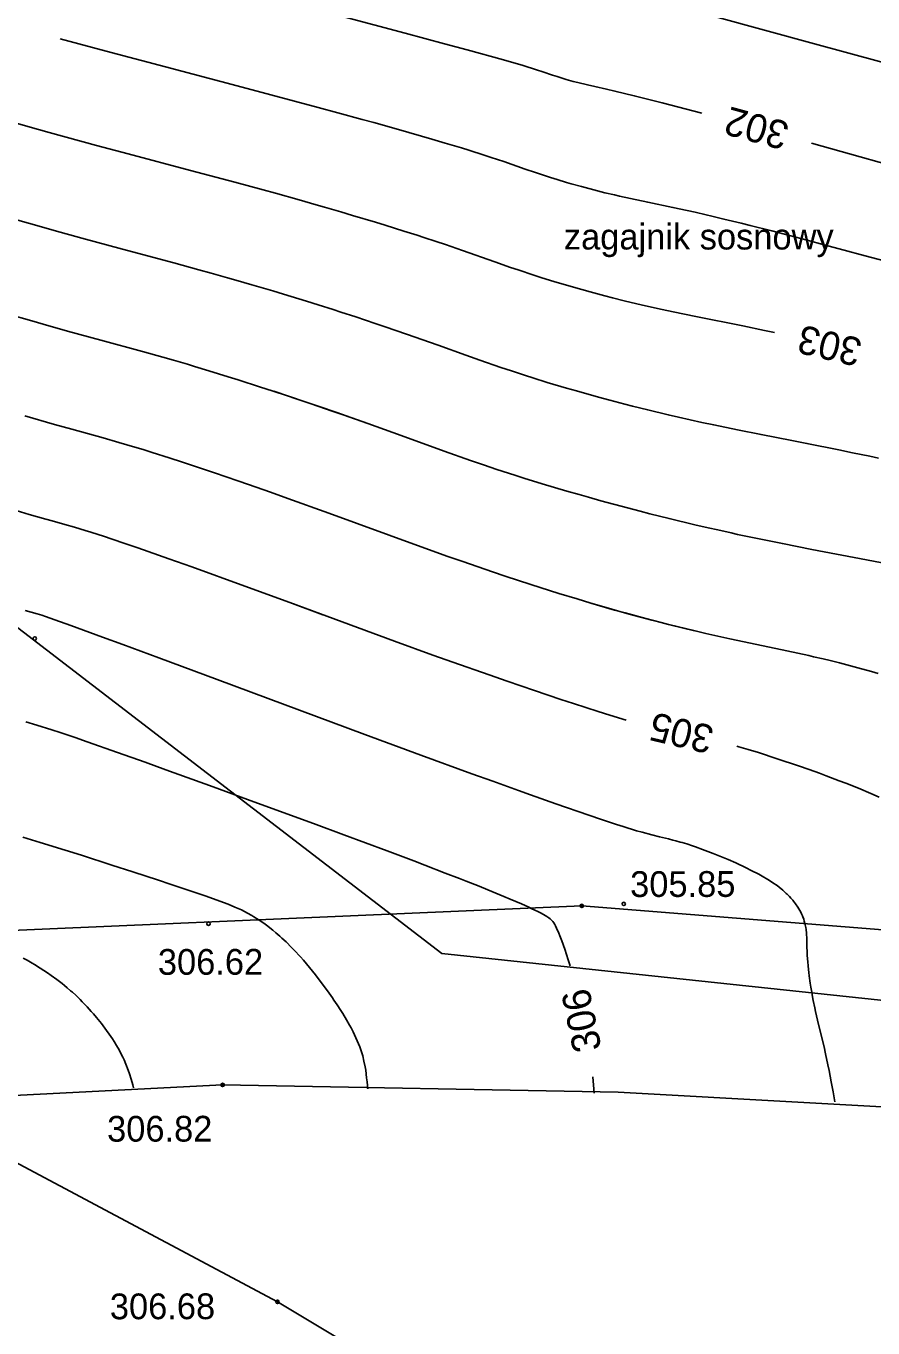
# Model space of a CAD drawing. Extents: x 7477803 to 7478145, y 5500698 to 5500984.
# Drawn here: x 7477935.87 to 7477958.24, y 5500809.46 to 5500843.86 of the extents above; entities that cross this region are included whole.
import ezdxf

# ---------------------------------------------------------------- set-up
doc = ezdxf.new("R2010")
doc.units = 0
for name, color, linetype in [('203-Punkt załamania granicy działki nie stabilizowany', 7, 'Continuous'), ('gr_dzialki', 7, 'Continuous'), ('gr_klasy', 7, 'Continuous'), ('jezdnia', 7, 'Continuous'), ('pkt_wys', 7, 'Continuous'), ('uwagi_projektanci', 7, 'Continuous'), ('warst_ciagla', 7, 'Continuous'), ('warst_opis', 7, 'Continuous'), ('warst_pogrub', 7, 'Continuous'), ('warst_przeryw', 7, 'Continuous')]:
    doc.layers.add(name, color=color, linetype=linetype)

# ---------------------------------------------------------------- blocks, each defined once
blk = doc.blocks.new('203')
blk.add_circle((0, 0), 0.045)
blk = doc.blocks.new('801_1')
at = {"layer": 'pkt_wys'}
blk.add_circle((0, 0), 0.045, dxfattribs=at)
blk.add_circle((0, 0), 0.045, dxfattribs=at)

msp = doc.modelspace()

# ---------------------------------------------------------------- linework, layer by layer
at = {"layer": 'gr_dzialki'}
for points in [[(7477950.55, 5500820.61), (7477930.18, 5500819.73)], [(7477982.46, 5500818.07), (7477950.55, 5500820.61)], [(7477942.51, 5500810.15), (7477926.59, 5500818.63)], [(7477942.51, 5500810.15), (7477965.87, 5500796.14)]]:
    msp.add_lwpolyline(points, dxfattribs=at)
at = {"layer": 'gr_klasy'}
for points in [[(7477930.18, 5500819.73), (7477950.55, 5500820.61)], [(7477950.55, 5500820.61), (7477982.46, 5500818.07)]]:
    msp.add_lwpolyline(points, dxfattribs=at)
at = {"layer": 'jezdnia'}
msp.add_lwpolyline([(7477875.926, 5500787.879), (7477876.814, 5500788.851), (7477888.353, 5500798.574), (7477893.52, 5500801.94), (7477899.965, 5500805.717), (7477906.333, 5500808.394), (7477918.837, 5500813.137), (7477925.266, 5500814.534), (7477933.655, 5500815.503), (7477941.064, 5500815.881), (7477951.515, 5500815.693), (7477966.065, 5500814.879), (7477981.427, 5500813.916), (7477996.758, 5500812.562), (7478008.149, 5500811.845)], dxfattribs=at)
at = {"layer": 'uwagi_projektanci'}
msp.add_lwpolyline([(7477973.16, 5500821.11), (7477976.42, 5500829.04), (7477976.7, 5500837.68), (7477975.34, 5500846.14), (7477969.75, 5500849.6), (7477966.4, 5500846.83), (7477944.18, 5500852.96), (7477931.39, 5500854.5), (7477929.49, 5500844.63), (7477930.21, 5500832.13), (7477946.85, 5500819.35), (7477963.16, 5500817.62)], close=True, dxfattribs=at)
at = {"layer": 'warst_ciagla'}
for points in [[(7477953.722, 5500841.553), (7477952.671, 5500841.827), (7477951.937, 5500842.014), (7477951.426, 5500842.139), (7477951.201, 5500842.191), (7477950.897, 5500842.256), (7477950.702, 5500842.3), (7477950.447, 5500842.363), (7477950.322, 5500842.396), (7477950.138, 5500842.449), (7477949.897, 5500842.523), (7477949.779, 5500842.562), (7477949.524, 5500842.649), (7477949.355, 5500842.704), (7477949.001, 5500842.813), (7477948.483, 5500842.963), (7477947.523, 5500843.229), (7477946.927, 5500843.391), (7477945.889, 5500843.669), (7477944.234, 5500844.107)], [(7477955.638, 5500835.757), (7477955.376, 5500835.814), (7477954.802, 5500835.934), (7477953.56, 5500836.185), (7477952.96, 5500836.309), (7477952.678, 5500836.369), (7477952.152, 5500836.486), (7477951.667, 5500836.601), (7477951.36, 5500836.677), (7477951.161, 5500836.729), (7477950.771, 5500836.833), (7477950.554, 5500836.893), (7477950.267, 5500836.975), (7477950.124, 5500837.016), (7477949.841, 5500837.101), (7477949.467, 5500837.217), (7477949.282, 5500837.276), (7477948.868, 5500837.413), (7477948.664, 5500837.482), (7477948.254, 5500837.626), (7477947.404, 5500837.926), (7477946.948, 5500838.083), (7477946.708, 5500838.164), (7477946.376, 5500838.274), (7477946.204, 5500838.329), (7477945.85, 5500838.442), (7477945.356, 5500838.596), (7477945.099, 5500838.675), (7477944.498, 5500838.855), (7477944.185, 5500838.948), (7477943.755, 5500839.072), (7477943.535, 5500839.136), (7477943.083, 5500839.264), (7477942.459, 5500839.438), (7477942.137, 5500839.527), (7477941.39, 5500839.731), (7477940.212, 5500840.045), (7477938.569, 5500840.481), (7477937.734, 5500840.705), (7477936.479, 5500841.049), (7477935.921, 5500841.204), (7477935.177, 5500841.414)], [(7477961.921, 5500839.278), (7477957.904, 5500840.402), (7477956.615, 5500840.759)], [(7477935.403, 5500836.246), (7477936.026, 5500836.065), (7477936.324, 5500835.979), (7477936.964, 5500835.799), (7477937.849, 5500835.556), (7477938.946, 5500835.258), (7477939.488, 5500835.107), (7477939.763, 5500835.028), (7477940.133, 5500834.92), (7477940.321, 5500834.864), (7477940.7, 5500834.75), (7477941.213, 5500834.592), (7477941.474, 5500834.51), (7477942.068, 5500834.32), (7477942.37, 5500834.222), (7477942.777, 5500834.087), (7477942.983, 5500834.018), (7477943.398, 5500833.877), (7477943.961, 5500833.684), (7477944.245, 5500833.584), (7477944.895, 5500833.354), (7477945.556, 5500833.115), (7477946.456, 5500832.79), (7477946.913, 5500832.626), (7477947.607, 5500832.383), (7477947.958, 5500832.263), (7477948.311, 5500832.145), (7477948.785, 5500831.991), (7477949.024, 5500831.915), (7477949.504, 5500831.766), (7477950.152, 5500831.572), (7477950.478, 5500831.477), (7477950.724, 5500831.407), (7477951.053, 5500831.315), (7477951.219, 5500831.27), (7477951.593, 5500831.169), (7477952.095, 5500831.037), (7477952.348, 5500830.972), (7477952.856, 5500830.845), (7477953.54, 5500830.682), (7477953.885, 5500830.602), (7477954.145, 5500830.543), (7477954.493, 5500830.466), (7477954.668, 5500830.428), (7477955.063, 5500830.344), (7477955.851, 5500830.182), (7477956.626, 5500830.029), (7477958.075, 5500829.751), (7477960.518, 5500829.287)], [(7477942.415, 5500834.207), (7477943.221, 5500833.938), (7477943.585, 5500833.813), (7477944.078, 5500833.643), (7477944.327, 5500833.555), (7477944.895, 5500833.354), (7477945.556, 5500833.115), (7477946.456, 5500832.79), (7477946.913, 5500832.626), (7477947.607, 5500832.383), (7477947.958, 5500832.263), (7477948.311, 5500832.145), (7477948.785, 5500831.991), (7477949.024, 5500831.915), (7477949.504, 5500831.766), (7477950.152, 5500831.572), (7477950.478, 5500831.477), (7477950.724, 5500831.407), (7477951.053, 5500831.315), (7477951.219, 5500831.27), (7477951.593, 5500831.169), (7477952.095, 5500831.037), (7477952.348, 5500830.972), (7477952.856, 5500830.845), (7477953.54, 5500830.682), (7477953.885, 5500830.602), (7477954.145, 5500830.543), (7477954.493, 5500830.466), (7477954.668, 5500830.428), (7477955.063, 5500830.344), (7477955.851, 5500830.182), (7477956.626, 5500830.029), (7477958.075, 5500829.751), (7477960.518, 5500829.287)], [(7477950.24, 5500819.03), (7477950.191, 5500819.188), (7477950.101, 5500819.465), (7477950.02, 5500819.692), (7477949.971, 5500819.819), (7477949.941, 5500819.893), (7477949.886, 5500820.019), (7477949.853, 5500820.088), (7477949.836, 5500820.118), (7477949.811, 5500820.16), (7477949.783, 5500820.198), (7477949.768, 5500820.217), (7477949.734, 5500820.251), (7477949.715, 5500820.268), (7477949.683, 5500820.294), (7477949.628, 5500820.332), (7477949.585, 5500820.359), (7477949.481, 5500820.417), (7477949.386, 5500820.465), (7477949.235, 5500820.538), (7477949.149, 5500820.578), (7477948.957, 5500820.664), (7477948.658, 5500820.793), (7477948.491, 5500820.863), (7477948.069, 5500821.036), (7477947.836, 5500821.13), (7477947.5, 5500821.263), (7477947.322, 5500821.333), (7477946.946, 5500821.479), (7477946.401, 5500821.688), (7477946.111, 5500821.799), (7477945.413, 5500822.062), (7477944.264, 5500822.49), (7477943.464, 5500822.785), (7477941.889, 5500823.362), (7477940.817, 5500823.753), (7477939.565, 5500824.207), (7477939.015, 5500824.405), (7477938.285, 5500824.665), (7477937.489, 5500824.946), (7477937.167, 5500825.057), (7477936.772, 5500825.19), (7477936.552, 5500825.262), (7477936.16, 5500825.386), (7477935.867, 5500825.475)], [(7477935.795, 5500819.231), (7477935.897, 5500819.175), (7477936.031, 5500819.098), (7477936.098, 5500819.059), (7477936.246, 5500818.967), (7477936.442, 5500818.839), (7477936.538, 5500818.773), (7477936.68, 5500818.67), (7477936.821, 5500818.562), (7477936.89, 5500818.506), (7477936.958, 5500818.449), (7477937.049, 5500818.371), (7477937.094, 5500818.332), (7477937.182, 5500818.25), (7477937.299, 5500818.138), (7477937.356, 5500818.081), (7477937.484, 5500817.948), (7477937.595, 5500817.825), (7477937.651, 5500817.761), (7477937.734, 5500817.661), (7477937.863, 5500817.5), (7477937.996, 5500817.321), (7477938.066, 5500817.223), (7477938.151, 5500817.1), (7477938.195, 5500817.033), (7477938.261, 5500816.927), (7477938.328, 5500816.812), (7477938.361, 5500816.75), (7477938.427, 5500816.617), (7477938.46, 5500816.546), (7477938.508, 5500816.432), (7477938.571, 5500816.267), (7477938.602, 5500816.178), (7477938.647, 5500816.036), (7477938.691, 5500815.884), (7477938.712, 5500815.804)], [(7477950.879, 5500815.66), (7477950.846, 5500816.092)]]:
    msp.add_lwpolyline(points, dxfattribs=at)
at = {"layer": 'warst_pogrub'}
for points in [[(7477951.724, 5500825.522), (7477951.29, 5500825.653), (7477950.983, 5500825.748), (7477950.335, 5500825.955), (7477949.996, 5500826.066), (7477949.298, 5500826.3), (7477948.582, 5500826.546), (7477948.101, 5500826.713), (7477947.145, 5500827.051), (7477946.619, 5500827.24), (7477945.601, 5500827.609), (7477944.63, 5500827.965), (7477942.841, 5500828.624), (7477941.646, 5500829.063), (7477940.251, 5500829.567), (7477939.639, 5500829.785), (7477938.827, 5500830.069), (7477938.507, 5500830.179), (7477938.12, 5500830.309), (7477937.943, 5500830.367), (7477937.586, 5500830.482), (7477937.429, 5500830.531), (7477937.147, 5500830.616), (7477936.893, 5500830.689), (7477936.564, 5500830.781), (7477936.391, 5500830.83), (7477935.954, 5500830.956), (7477935.266, 5500831.161)], [(7477943.712, 5500828.303), (7477942.841, 5500828.624), (7477941.646, 5500829.063), (7477940.251, 5500829.567), (7477939.639, 5500829.785), (7477938.827, 5500830.069), (7477938.507, 5500830.179), (7477938.12, 5500830.309), (7477937.943, 5500830.367), (7477937.586, 5500830.482), (7477937.429, 5500830.531), (7477937.147, 5500830.616), (7477936.893, 5500830.689), (7477936.564, 5500830.781), (7477936.391, 5500830.83), (7477935.954, 5500830.956), (7477935.266, 5500831.161)], [(7477958.404, 5500823.488), (7477958.186, 5500823.582), (7477957.857, 5500823.72), (7477957.523, 5500823.854), (7477957.353, 5500823.92), (7477957.006, 5500824.052), (7477956.828, 5500824.118), (7477956.555, 5500824.216), (7477956.274, 5500824.314), (7477955.715, 5500824.501), (7477955.215, 5500824.663), (7477954.946, 5500824.746), (7477954.703, 5500824.817), (7477954.643, 5500824.832)]]:
    msp.add_lwpolyline(points, dxfattribs=at)
at = {"layer": 'warst_przeryw'}
for points in [[(7477961.942, 5500841.958), (7477956.699, 5500843.391), (7477952.737, 5500844.468)], [(7477936.776, 5500843.521), (7477938.119, 5500843.158), (7477939.553, 5500842.777), (7477941.444, 5500842.28), (7477942.341, 5500842.043), (7477943.588, 5500841.709), (7477944.103, 5500841.569), (7477944.751, 5500841.392), (7477945.059, 5500841.306), (7477945.712, 5500841.123), (7477946.59, 5500840.871), (7477946.94, 5500840.767), (7477947.369, 5500840.638), (7477947.568, 5500840.577), (7477947.975, 5500840.448), (7477948.158, 5500840.388), (7477948.489, 5500840.277), (7477949.059, 5500840.078), (7477949.324, 5500839.987), (7477949.723, 5500839.857), (7477949.904, 5500839.801), (7477950.146, 5500839.728), (7477950.269, 5500839.692), (7477950.546, 5500839.614), (7477950.97, 5500839.503), (7477951.16, 5500839.455), (7477951.417, 5500839.394), (7477951.546, 5500839.364), (7477951.84, 5500839.299), (7477952.292, 5500839.204), (7477952.957, 5500839.066), (7477953.337, 5500838.984), (7477953.542, 5500838.938), (7477953.832, 5500838.871), (7477953.984, 5500838.835), (7477954.303, 5500838.759), (7477954.757, 5500838.647), (7477954.997, 5500838.587), (7477955.568, 5500838.443), (7477956.505, 5500838.199), (7477956.952, 5500838.081), (7477957.578, 5500837.914), (7477957.903, 5500837.826), (7477958.667, 5500837.618)], [(7477935.592, 5500838.744), (7477936.276, 5500838.55), (7477936.611, 5500838.456), (7477937.349, 5500838.252), (7477938.417, 5500837.963), (7477939.779, 5500837.599), (7477940.439, 5500837.419), (7477940.765, 5500837.328), (7477941.196, 5500837.207), (7477941.41, 5500837.146), (7477941.834, 5500837.023), (7477942.392, 5500836.859), (7477942.669, 5500836.776), (7477943.283, 5500836.588), (7477943.586, 5500836.493), (7477943.987, 5500836.366), (7477944.185, 5500836.302), (7477944.579, 5500836.174), (7477945.097, 5500836.002), (7477945.353, 5500835.915), (7477945.921, 5500835.719), (7477946.757, 5500835.422), (7477947.492, 5500835.159), (7477947.859, 5500835.029), (7477948.413, 5500834.838), (7477948.693, 5500834.745), (7477949.068, 5500834.622), (7477949.257, 5500834.562), (7477949.637, 5500834.444), (7477950.15, 5500834.291), (7477950.408, 5500834.216), (7477950.995, 5500834.051), (7477951.291, 5500833.971), (7477951.688, 5500833.867), (7477951.888, 5500833.816), (7477952.291, 5500833.715), (7477952.833, 5500833.586), (7477952.833, 5500833.586), (7477953.106, 5500833.523), (7477953.725, 5500833.385), (7477954.038, 5500833.318), (7477954.665, 5500833.189), (7477955.288, 5500833.065), (7477956.102, 5500832.906), (7477956.496, 5500832.829), (7477957.343, 5500832.659), (7477957.701, 5500832.586), (7477958.162, 5500832.49), (7477958.385, 5500832.443)], [(7477953.53, 5500827.878), (7477953.238, 5500827.948), (7477952.845, 5500828.046), (7477952.645, 5500828.097), (7477952.243, 5500828.203), (7477951.696, 5500828.351), (7477951.419, 5500828.429), (7477950.786, 5500828.612), (7477950.427, 5500828.72), (7477949.943, 5500828.868), (7477949.697, 5500828.945), (7477949.202, 5500829.103), (7477948.529, 5500829.324), (7477948.188, 5500829.438), (7477947.409, 5500829.707), (7477947.013, 5500829.846), (7477946.215, 5500830.132), (7477943.868, 5500830.989), (7477942.786, 5500831.379), (7477942.329, 5500831.541), (7477941.745, 5500831.746), (7477941.463, 5500831.844), (7477940.853, 5500832.053), (7477940.562, 5500832.151), (7477940.186, 5500832.276), (7477940.004, 5500832.336), (7477939.651, 5500832.45), (7477939.205, 5500832.591), (7477938.992, 5500832.657), (7477938.537, 5500832.794), (7477938.322, 5500832.857), (7477937.909, 5500832.975), (7477937.078, 5500833.205), (7477936.62, 5500833.333), (7477935.837, 5500833.559)], [(7477958.377, 5500826.755), (7477958.2, 5500826.805), (7477957.842, 5500826.904), (7477957.357, 5500827.03), (7477957.11, 5500827.092), (7477956.923, 5500827.137), (7477956.671, 5500827.196), (7477956.545, 5500827.225), (7477956.257, 5500827.289), (7477955.672, 5500827.414), (7477954.458, 5500827.669), (7477953.827, 5500827.809), (7477953.506, 5500827.884), (7477953.071, 5500827.99), (7477952.851, 5500828.045), (7477952.405, 5500828.16), (7477951.799, 5500828.323), (7477951.491, 5500828.409), (7477951.258, 5500828.475), (7477950.944, 5500828.566), (7477950.786, 5500828.612), (7477950.427, 5500828.72), (7477949.943, 5500828.868), (7477949.697, 5500828.945), (7477949.202, 5500829.103), (7477948.529, 5500829.324), (7477948.188, 5500829.438), (7477947.409, 5500829.707), (7477947.013, 5500829.846), (7477946.215, 5500830.132), (7477943.868, 5500830.989), (7477942.786, 5500831.379), (7477942.329, 5500831.541), (7477941.745, 5500831.746), (7477941.463, 5500831.844), (7477940.853, 5500832.053), (7477940.562, 5500832.151), (7477940.186, 5500832.276), (7477940.004, 5500832.336), (7477939.651, 5500832.45), (7477939.205, 5500832.591), (7477938.992, 5500832.657), (7477938.537, 5500832.794), (7477938.322, 5500832.857), (7477937.909, 5500832.975), (7477937.078, 5500833.205), (7477936.62, 5500833.333), (7477935.837, 5500833.559)], [(7477935.849, 5500828.42), (7477936.161, 5500828.327), (7477936.285, 5500828.29), (7477936.385, 5500828.258), (7477936.635, 5500828.17), (7477937.053, 5500828.02), (7477937.888, 5500827.715), (7477938.424, 5500827.517), (7477939.376, 5500827.165), (7477940.923, 5500826.591), (7477941.815, 5500826.26), (7477944.816, 5500825.144), (7477946.303, 5500824.594), (7477947.649, 5500824.102), (7477948.197, 5500823.903), (7477948.878, 5500823.659), (7477949.197, 5500823.545), (7477949.865, 5500823.309), (7477950.735, 5500823.008), (7477951.07, 5500822.895), (7477951.469, 5500822.764), (7477951.647, 5500822.707), (7477951.997, 5500822.599), (7477952.146, 5500822.556), (7477952.4, 5500822.487), (7477952.607, 5500822.435), (7477952.842, 5500822.379), (7477952.952, 5500822.351), (7477953.035, 5500822.33), (7477953.148, 5500822.299), (7477953.205, 5500822.282), (7477953.321, 5500822.247), (7477953.478, 5500822.197), (7477953.558, 5500822.17), (7477953.741, 5500822.105), (7477954.023, 5500821.998), (7477954.152, 5500821.947), (7477954.326, 5500821.874), (7477954.415, 5500821.836), (7477954.617, 5500821.746), (7477954.892, 5500821.618), (7477955.028, 5500821.551), (7477955.229, 5500821.446), (7477955.358, 5500821.374), (7477955.421, 5500821.337), (7477955.511, 5500821.281), (7477955.598, 5500821.223), (7477955.708, 5500821.146), (7477955.76, 5500821.107), (7477955.858, 5500821.027), (7477955.9, 5500820.991), (7477955.953, 5500820.942), (7477955.978, 5500820.918), (7477956.034, 5500820.862), (7477956.073, 5500820.82), (7477956.123, 5500820.763), (7477956.146, 5500820.734), (7477956.196, 5500820.669), (7477956.257, 5500820.58), (7477956.285, 5500820.535), (7477956.335, 5500820.444), (7477956.354, 5500820.403), (7477956.379, 5500820.348), (7477956.39, 5500820.32), (7477956.413, 5500820.257), (7477956.428, 5500820.21), (7477956.445, 5500820.145), (7477956.452, 5500820.113), (7477956.466, 5500820.039), (7477956.473, 5500819.99), (7477956.484, 5500819.889), (7477956.493, 5500819.734), (7477956.498, 5500819.518), (7477956.502, 5500819.406), (7477956.506, 5500819.32), (7477956.514, 5500819.203), (7477956.518, 5500819.143), (7477956.529, 5500819.021), (7477956.548, 5500818.853), (7477956.559, 5500818.767), (7477956.587, 5500818.569), (7477956.603, 5500818.467), (7477956.626, 5500818.328), (7477956.639, 5500818.258), (7477956.666, 5500818.114), (7477956.705, 5500817.918), (7477956.727, 5500817.818), (7477956.779, 5500817.588), (7477956.866, 5500817.228), (7477956.949, 5500816.885), (7477956.991, 5500816.704), (7477957.053, 5500816.415), (7477957.084, 5500816.264), (7477957.141, 5500815.964), (7477957.188, 5500815.701), (7477957.232, 5500815.439)], [(7477935.783, 5500822.43), (7477936.24, 5500822.29), (7477936.905, 5500822.083), (7477937.332, 5500821.948), (7477938.139, 5500821.689), (7477938.695, 5500821.509), (7477939.369, 5500821.288), (7477939.677, 5500821.186), (7477940.103, 5500821.044), (7477940.603, 5500820.873), (7477940.824, 5500820.796), (7477941.09, 5500820.701), (7477941.213, 5500820.654), (7477941.389, 5500820.582), (7477941.559, 5500820.505), (7477941.642, 5500820.464), (7477941.725, 5500820.42), (7477941.836, 5500820.357), (7477941.891, 5500820.324), (7477942.002, 5500820.254), (7477942.148, 5500820.153), (7477942.221, 5500820.1), (7477942.386, 5500819.972), (7477942.467, 5500819.904), (7477942.576, 5500819.809), (7477942.631, 5500819.76), (7477942.739, 5500819.659), (7477942.884, 5500819.516), (7477942.956, 5500819.441), (7477943.117, 5500819.265), (7477943.198, 5500819.174), (7477943.358, 5500818.984), (7477943.514, 5500818.79), (7477943.615, 5500818.659), (7477943.808, 5500818.401), (7477943.876, 5500818.306), (7477943.963, 5500818.182), (7477944.005, 5500818.121), (7477944.086, 5500818.001), (7477944.188, 5500817.846), (7477944.235, 5500817.77), (7477944.336, 5500817.603), (7477944.418, 5500817.46), (7477944.457, 5500817.39), (7477944.511, 5500817.285), (7477944.586, 5500817.127), (7477944.655, 5500816.967), (7477944.686, 5500816.884), (7477944.739, 5500816.731), (7477944.763, 5500816.649), (7477944.797, 5500816.512), (7477944.828, 5500816.356), (7477944.843, 5500816.269), (7477944.868, 5500816.073), (7477944.88, 5500815.963), (7477944.895, 5500815.78)]]:
    msp.add_lwpolyline(points, dxfattribs=at)

# ---------------------------------------------------------------- block references
at = {"layer": '203-Punkt załamania granicy działki nie stabilizowany'}
for p in [(7477950.55, 5500820.61), (7477942.51, 5500810.15)]:
    msp.add_blockref('203', p, dxfattribs=at)
at = {"layer": 'pkt_wys', "rotation": 0.0626175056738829}
for p in [(7477936.101, 5500827.676), (7477951.659, 5500820.663), (7477940.69, 5500820.141), (7477941.064, 5500815.881)]:
    msp.add_blockref('801_1', p, dxfattribs=at)

# ---------------------------------------------------------------- texts
at = {"layer": 'pkt_wys'}
for s, p in [('305.85', (7477951.828, 5500820.847)), ('306.62', (7477939.354, 5500818.791)), ('306.82', (7477938.012, 5500814.382)), ('306.68', (7477938.085, 5500809.69))]:
    msp.add_text(s, height=0.68, rotation=0.0626, dxfattribs=at).set_placement(p)
at = {"layer": 'uwagi_projektanci'}
msp.add_text('zagajnik sosnowy', height=0.68, dxfattribs=at).set_placement((7477950.077, 5500837.954))
at = {"layer": 'warst_opis'}
for s, rotation, p in [('302', 164.6634, (7477956.073, 5500841.297)), ('303', 166.6194, (7477957.997, 5500835.581)), ('305', 166.6915, (7477954.083, 5500825.35)), ('306', 101.6618, (7477951.077, 5500816.833))]:
    msp.add_text(s, height=0.75, rotation=rotation, dxfattribs=at).set_placement(p)

doc.saveas('drawing.dxf')
